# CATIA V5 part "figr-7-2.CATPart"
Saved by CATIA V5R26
Part number: Part1
Bounding box of the stored display mesh (mm): x -50 to 50, y -75 to 75, z 0 to 10
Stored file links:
  D:\_Deepak\CATIA\CATIA V5-6R2016_Deepak\Resources\Part files\Partfiles\c07_catia_v5_6r2016_prt\figr-7-2.CATPart
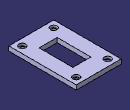
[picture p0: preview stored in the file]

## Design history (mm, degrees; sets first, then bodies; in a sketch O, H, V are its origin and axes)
Body1 (main body)
  Sketch1 on xy-plane, origin (0, 0, 0), H (1, 0, 0), V (0, 1, 0)
    line L1 (-50, 75) -> (50, 75)
    line L2 (50, 75) -> (50, -75)
    line L3 (50, -75) -> (-50, -75)
    line L4 (-50, -75) -> (-50, 75)
    axis line L5 (50, -75) -> (-50, 75)
    length L3 = 100
    length L2 = 150
    horizontal: L1 H, L3 H
    vertical: L2 V, L4 V
    midpoint: O L5
  Pad1: profile Sketch1, direction (0, 0, 1), length 10
  Sketch2 on face of Pad1, origin (0, 0, 10), H (1, 0, 0), V (0, 1, 0)
    line L1 (-20, 37.5) -> (20, 37.5)
    line L2 (20, 37.5) -> (20, -37.5)
    line L3 (20, -37.5) -> (-20, -37.5)
    line L4 (-20, -37.5) -> (-20, 37.5)
    axis line L5 (20, -37.5) -> (-20, 37.5)
    length L3 = 40
    length L2 = 75
    horizontal: L1 H, L3 H
    vertical: L2 V, L4 V
    midpoint: O L5
  Pocket1: profile Sketch2, direction (0, 0, -1), through (limit type 3)
  Sketch3 on face of Pad1, origin (-33.8832, 14.5619, 10), H (1, 0, 0), V (0, 1, 0)
    point P1 (68.8832, -74.5619)
    reference projected line E1 (-16.1168, -89.5619) -> (83.8832, -89.5619) from edge [face of Pad1 | face of Pad1]
    reference projected line E2 (83.8832, -89.5619) -> (83.8832, 60.4381) from edge [face of Pad1 | face of Pad1]
    distance P1 E1 = 15
    distance P1 E2 = 15
  Hole1: placed by Sketch3, at (35, -60, 10) direction (0, 0, -1), diameter 10, through (limit type 3), counterbore diameter 15, counterbore depth 5
  RectPattern1: of Hole1, direction 1 instances 2, spacing 70, along edge [face of Pad1 | face of Pad1] reversed, direction 2 instances 2, spacing 120, along edge [face of Pad1 | face of Pad1]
